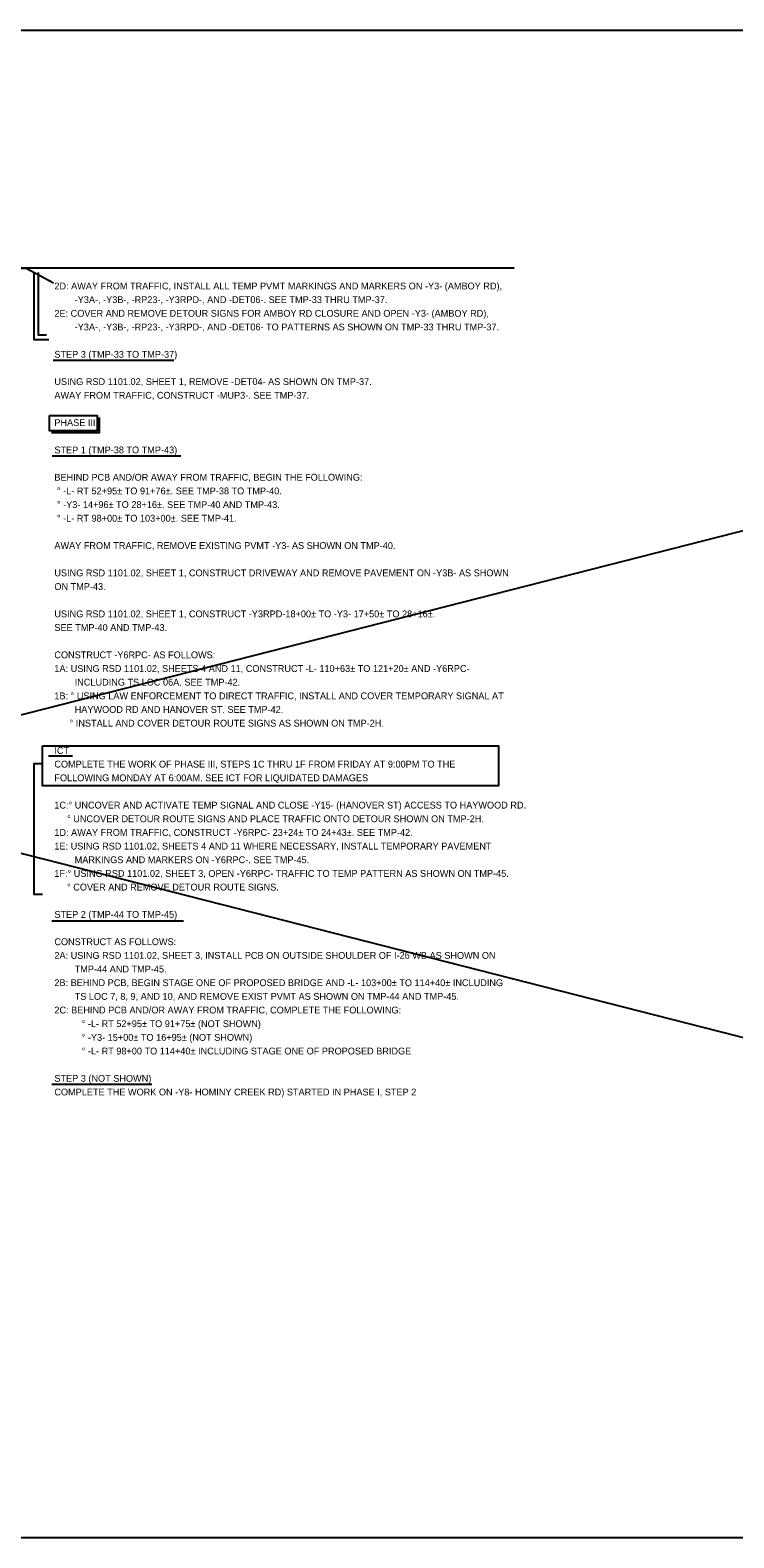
# Model space of a CAD drawing. Extents: x 2483905 to 2494512, y 366160 to 372330.
# Drawn here: x 2490016 to 2490737, y 368441 to 369986 of the extents above; entities that cross this region are included whole.
import ezdxf

# ---------------------------------------------------------------- set-up
doc = ezdxf.new("R2010")
doc.units = 0
for name, color, linetype in [('Scratch_Level_4', 7, 'Continuous'), ('Scratch_Level_6', 7, 'Continuous'), ('TC SHEET BORDER LINE THIN', 7, 'Continuous')]:
    doc.layers.add(name, color=color, linetype=linetype)

msp = doc.modelspace()

# ---------------------------------------------------------------- linework, layer by layer
at = {"layer": 'Scratch_Level_4'}
for p, q in [((2486701.2, 368441.1), (2492754.6, 369986.2)), ((2486701.2, 369986.2), (2492754.6, 368441.1))]:
    msp.add_line(p, q, dxfattribs=at)
msp.add_lwpolyline([(2486701.2, 369986.2), (2492754.6, 369986.2), (2492754.6, 368441.1), (2486701.2, 368441.1)], close=True, dxfattribs=at)
at = {"layer": 'Scratch_Level_6'}
msp.add_lwpolyline([(2489011.6, 369742.3), (2489039.5, 369727.3), (2489511.6, 369742.3), (2489539.5, 369727.3), (2490011.6, 369742.3), (2490039.5, 369727.3)], dxfattribs=at)
at = {"layer": 'TC SHEET BORDER LINE THIN'}
for p, q in [((2490511.6, 369742.3), (2489011.6, 369742.3)), ((2490039, 369648.1), (2490162.8, 369648.1)), ((2490038.2, 369549.9), (2490038.2, 369549.9)), ((2490038.2, 369549.9), (2490170.1, 369549.9)), ((2490034.4, 369242.6), (2490058.8, 369242.6)), ((2490037.7, 369073.5), (2490172.6, 369073.5)), ((2490037.9, 368906.2), (2490140.2, 368906.2))]:
    msp.add_line(p, q, dxfattribs=at)
for points in [[(2490019.4, 369738), (2490019.4, 369669.3), (2490034.8, 369669.3)], [(2490023.9, 369738), (2490023.9, 369674.1), (2490032.5, 369674.1)], [(2490086.4, 369589.2), (2490086.4, 369573.6), (2490037.4, 369573.6)], [(2490028.2, 369234.3), (2490019.5, 369234.3), (2490019.5, 369100.8), (2490028.2, 369100.8)]]:
    msp.add_lwpolyline(points, dxfattribs=at)
for points in [[(2490035.4, 369591.2), (2490084.4, 369591.2), (2490084.4, 369575.6), (2490035.4, 369575.6)], [(2490028.2, 369252.9), (2490495.5, 369252.9), (2490495.5, 369211.8), (2490028.2, 369211.8)]]:
    msp.add_lwpolyline(points, close=True, dxfattribs=at)

# ---------------------------------------------------------------- texts
for s, p in [('2D: AWAY FROM TRAFFIC, INSTALL ALL TEMP PVMT MARKINGS AND MARKERS ON -Y3- (AMBOY RD),', (2490040.4, 369720.5)), ('        -Y3A-, -Y3B-, -RP23-, -Y3RPD-, AND -DET06-. SEE TMP-33 THRU TMP-37.', (2490040.4, 369706.5)), ('2E: COVER AND REMOVE DETOUR SIGNS FOR AMBOY RD CLOSURE AND OPEN -Y3- (AMBOY RD),', (2490040.4, 369692.5)), ('        -Y3A-, -Y3B-, -RP23-, -Y3RPD-, AND -DET06- TO PATTERNS AS SHOWN ON TMP-33 THRU TMP-37.', (2490040.4, 369678.5)), ('STEP 3 (TMP-33 TO TMP-37)', (2490040.4, 369650.5)), ('USING RSD 1101.02, SHEET 1, REMOVE -DET04- AS SHOWN ON TMP-37.', (2490040.4, 369622.5)), ('AWAY FROM TRAFFIC, CONSTRUCT -MUP3-. SEE TMP-37.', (2490040.4, 369608.5)), ('PHASE III', (2490040.4, 369580.5)), ('STEP 1 (TMP-38 TO TMP-43)', (2490040.4, 369552.5)), ('BEHIND PCB AND/OR AWAY FROM TRAFFIC, BEGIN THE FOLLOWING:', (2490040.4, 369524.5)), (' ° -L- RT 52+95± TO 91+76±. SEE TMP-38 TO TMP-40.', (2490040.4, 369510.5)), (' ° -Y3- 14+96± TO 28+16±. SEE TMP-40 AND TMP-43.', (2490040.4, 369496.5)), (' ° -L- RT 98+00± TO 103+00±. SEE TMP-41.', (2490040.4, 369482.5)), ('AWAY FROM TRAFFIC, REMOVE EXISTING PVMT -Y3- AS SHOWN ON TMP-40.', (2490040.4, 369454.5)), ('USING RSD 1101.02, SHEET 1, CONSTRUCT DRIVEWAY AND REMOVE PAVEMENT ON -Y3B- AS SHOWN ', (2490040.4, 369426.5)), ('ON TMP-43.', (2490040.4, 369412.5)), ('USING RSD 1101.02, SHEET 1, CONSTRUCT -Y3RPD-18+00± TO -Y3- 17+50± TO 28+16±.', (2490040.4, 369384.5)), ('SEE TMP-40 AND TMP-43.', (2490040.4, 369370.5)), ('CONSTRUCT -Y6RPC- AS FOLLOWS:', (2490040.4, 369342.5)), ('1A: USING RSD 1101.02, SHEETS 4 AND 11, CONSTRUCT -L- 110+63± TO 121+20± AND -Y6RPC-  ', (2490040.4, 369328.5)), ('        INCLUDING TS LOC 06A. SEE TMP-42.', (2490040.4, 369314.5)), ('1B: ° USING LAW ENFORCEMENT TO DIRECT TRAFFIC, INSTALL AND COVER TEMPORARY SIGNAL AT', (2490040.4, 369300.5)), ('        HAYWOOD RD AND HANOVER ST. SEE TMP-42.', (2490040.4, 369286.5)), ('      ° INSTALL AND COVER DETOUR ROUTE SIGNS AS SHOWN ON TMP-2H.', (2490040.4, 369272.5)), ('ICT ', (2490040.4, 369244.5)), ('COMPLETE THE WORK OF PHASE III, STEPS 1C THRU 1F FROM FRIDAY AT 9:00PM TO THE', (2490040.4, 369230.5)), ('FOLLOWING MONDAY AT 6:00AM. SEE ICT FOR LIQUIDATED DAMAGES', (2490040.4, 369216.5)), ('1C:° UNCOVER AND ACTIVATE TEMP SIGNAL AND CLOSE -Y15- (HANOVER ST) ACCESS TO HAYWOOD RD.', (2490040.4, 369188.5)), ('     ° UNCOVER DETOUR ROUTE SIGNS AND PLACE TRAFFIC ONTO DETOUR SHOWN ON TMP-2H.', (2490040.4, 369174.5)), ('1D: AWAY FROM TRAFFIC, CONSTRUCT -Y6RPC- 23+24± TO 24+43±. SEE TMP-42.', (2490040.4, 369160.5)), ('1E: USING RSD 1101.02, SHEETS 4 AND 11 WHERE NECESSARY, INSTALL TEMPORARY PAVEMENT', (2490040.4, 369146.5)), ('        MARKINGS AND MARKERS ON -Y6RPC-. SEE TMP-45.', (2490040.4, 369132.5)), ('1F:° USING RSD 1101.02, SHEET 3, OPEN -Y6RPC- TRAFFIC TO TEMP PATTERN AS SHOWN ON TMP-45.', (2490040.4, 369118.5)), ('     ° COVER AND REMOVE DETOUR ROUTE SIGNS.', (2490040.4, 369104.5)), ('STEP 2 (TMP-44 TO TMP-45)', (2490040.4, 369076.5)), ('CONSTRUCT AS FOLLOWS:', (2490040.4, 369048.5)), ('2A: USING RSD 1101.02, SHEET 3, INSTALL PCB ON OUTSIDE SHOULDER OF I-26 WB AS SHOWN ON ', (2490040.4, 369034.5)), ('        TMP-44 AND TMP-45.', (2490040.4, 369020.5)), ('2B: BEHIND PCB, BEGIN STAGE ONE OF PROPOSED BRIDGE AND -L- 103+00± TO 114+40± INCLUDING', (2490040.4, 369006.5)), ('        TS LOC 7, 8, 9, AND 10, AND REMOVE EXIST PVMT AS SHOWN ON TMP-44 AND TMP-45.', (2490040.4, 368992.5)), ('2C: BEHIND PCB AND/OR AWAY FROM TRAFFIC, COMPLETE THE FOLLOWING:', (2490040.4, 368978.5)), ('° -L- RT 52+95± TO 91+75± (NOT SHOWN)', (2490068.4, 368964.5)), ('° -Y3- 15+00± TO 16+95± (NOT SHOWN)', (2490068.4, 368950.5)), ('° -L- RT 98+00 TO 114+40± INCLUDING STAGE ONE OF PROPOSED BRIDGE', (2490068.4, 368936.5)), ('STEP 3 (NOT SHOWN)', (2490040.4, 368908.5)), ('COMPLETE THE WORK ON -Y8- HOMINY CREEK RD) STARTED IN PHASE I, STEP 2', (2490040.4, 368894.5))]:
    msp.add_text(s, height=7, dxfattribs=at).set_placement(p)

doc.saveas('drawing.dxf')
